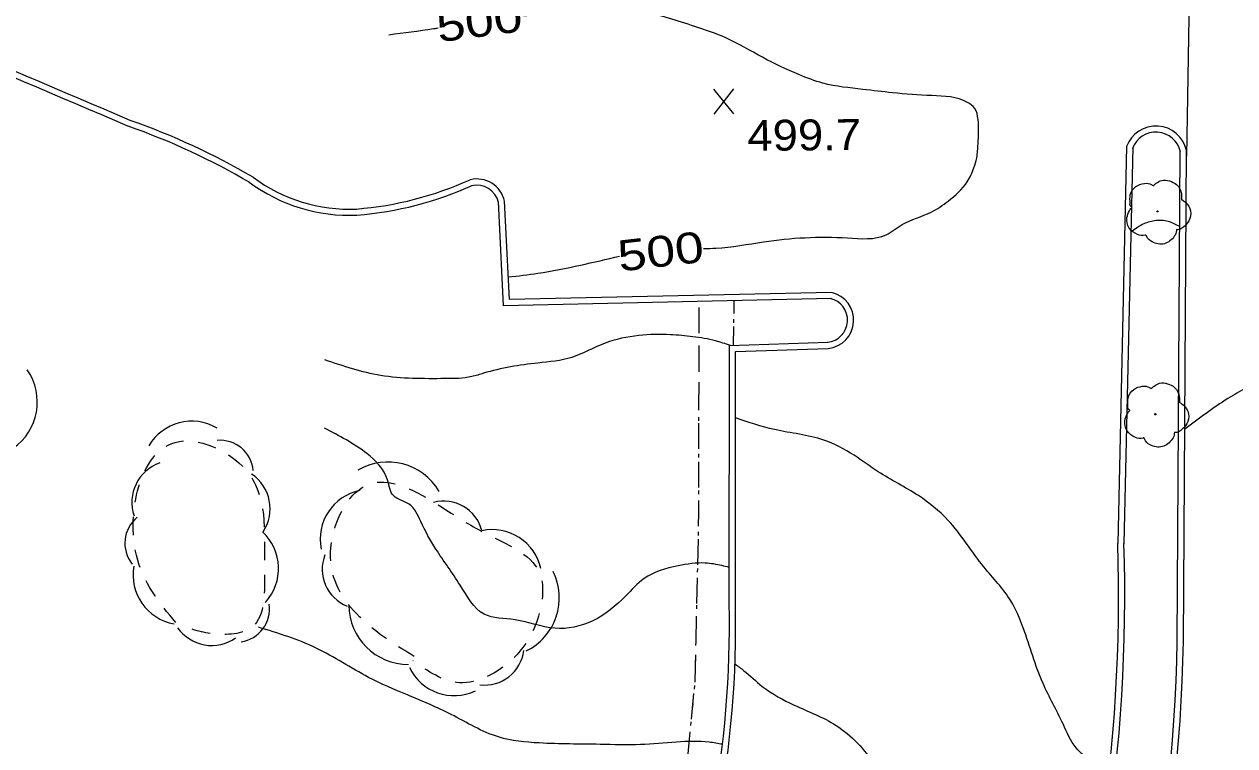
# Model space of a CAD drawing. Extents: x 2362213 to 2366494, y 6968794 to 6978110.
# Drawn here: x 2364033.7 to 2364221.6, y 6973266.2 to 6973378.3 of the extents above; entities that cross this region are included whole.
import ezdxf
from ezdxf.enums import TextEntityAlignment as Align

# ---------------------------------------------------------------- set-up
doc = ezdxf.new("R2010")
doc.units = 0
doc.header["$LTSCALE"] = 1.9
doc.linetypes.add('DOTTED', pattern=[1.5, 0.3, -1.2])
doc.linetypes.add('SHORT_DASHED', pattern=[2.7, 1.5, -1.2])
for name, color, linetype, lineweight in [('13', 7, 'Continuous', 13), ('2', 7, 'Continuous', 25), ('29', 7, 'Continuous', 13), ('31', 7, 'Continuous', 25), ('35', 7, 'Continuous', 13)]:
    doc.layers.add(name, color=color, linetype=linetype, lineweight=lineweight)

msp = doc.modelspace()

# ---------------------------------------------------------------- linework, layer by layer
at = {"layer": '13'}
for p, q in [((2364138.453, 6973330.3), (2364138.465, 6973334.301)), ((2364143.856, 6973335.322), (2364143.825, 6973333.322)), ((2364143.784, 6973331.321), (2364143.732, 6973328.391)), ((2364138.44, 6973324.301), (2364138.452, 6973328.3)), ((2364138.434, 6973312.299), (2364138.426, 6973316.3)), ((2364138.431, 6973306.299), (2364138.433, 6973310.299)), ((2364138.246, 6973294.297), (2364138.338, 6973298.299)), ((2364138.103, 6973288.295), (2364138.195, 6973292.296)), ((2364137.97, 6973282.294), (2364138.062, 6973286.295)), ((2364137.837, 6973276.293), (2364137.929, 6973280.293)), ((2364137.265, 6973270.316), (2364137.656, 6973274.301)), ((2364136.692, 6973264.341), (2364137.074, 6973268.325))]:
    msp.add_line(p, q, dxfattribs=at)
at = {"layer": '13', "linetype": 'DOTTED'}
msp.add_line((2364143.856, 6973335.322), (2364143.732, 6973328.391), dxfattribs=at)
msp.add_lwpolyline([(2364128.747, 6973249.094), (2364134.216, 6973248.096), (2364136.355, 6973260.807), (2364137.829, 6973276.053), (2364138.428, 6973302.43), (2364138.428, 6973319.271), (2364138.466, 6973335.201)], dxfattribs=at)
at = {"layer": '13'}
for points in [[(2364138.427, 6973318.301), (2364138.428, 6973319.271), (2364138.439, 6973322.301)], [(2364138.378, 6973300.299), (2364138.428, 6973302.43), (2364138.43, 6973304.299)]]:
    msp.add_lwpolyline(points, dxfattribs=at)
at = {"layer": '2'}
for p, q in [((2364214.964, 6973407.354), (2364214.125, 6973357.812)), ((2364204.831, 6973359.284), (2364203.448, 6973297.589)), ((2364205.791, 6973359.263), (2364204.408, 6973297.568)), ((2364212.704, 6973282.375), (2364213.167, 6973358.673)), ((2364213.664, 6973282.374), (2364214.127, 6973358.672))]:
    msp.add_line(p, q, dxfattribs=at)
for points in [[(2364159.034, 6973335.657), (2364108.082, 6973334.521), (2364107.278, 6973350.755)], [(2364159.015, 6973336.617), (2364108.993, 6973335.5), (2364108.237, 6973350.804)], [(2364143.125, 6973288.233), (2364143.152, 6973328.375), (2364158.448, 6973328.881)], [(2364144.085, 6973288.232), (2364144.111, 6973327.444), (2364158.477, 6973327.921)]]:
    msp.add_lwpolyline(points, dxfattribs=at)
for centre, radius, start, end in [((2297834.183, 6817959.898), 168921.461, 66.92161, 66.96926), ((2297834.183, 6817959.898), 168922.421, 66.92161, 66.96926), ((2364013.639, 6973259.63), 108.991, 59.65961, 70.61999), ((2364013.639, 6973259.63), 109.951, 59.65961, 70.61999), ((2364209.392, 6973357.644), 4.846, 12.25931, 160.2178), ((2364209.392, 6973357.644), 3.886, 12.25931, 160.2178), ((2364084.175, 6973374.709), 26.107, 233.39337, 272.44355), ((2364084.175, 6973374.709), 25.147, 233.39337, 272.44355), ((2364080.988, 6973402.517), 53.103, 274.60096, 294.36447), ((2364080.988, 6973402.517), 54.063, 274.60096, 294.36447), ((2364103.895, 6973349.8), 4.456, 13.01878, 102.97451), ((2364103.895, 6973349.8), 3.496, 13.01878, 102.97451), ((2364158.046, 6973332.312), 4.412, 275.6107, 77.31998), ((2364158.046, 6973332.312), 3.452, 275.6107, 77.31998), ((2363953.796, 6973289.236), 249.792, 340.34724, 1.91609), ((2363953.796, 6973289.236), 250.751, 340.34724, 1.91609), ((2363987.106, 6973284.72), 156.058, 349.19153, 1.28189), ((2363987.106, 6973284.72), 157.018, 349.19153, 1.28189), ((2363956.023, 6973287.24), 256.726, 337.03921, 358.91818), ((2363956.023, 6973287.24), 257.686, 337.03921, 358.91818)]:
    msp.add_arc(centre, radius, start, end, dxfattribs=at)
at = {"layer": '29'}
for centre in [(2364209.627, 6973349.22), (2364209.307, 6973317.695)]:
    msp.add_circle(centre, 0.1, dxfattribs=at)
for centre, radius, start, end in [((2364026.934, 6973319.593), 8.752, 304.69454, 34.69454), ((2364059.679, 6973308.859), 7.753, 59.56106, 149.56106), ((2364064.079, 6973308.476), 5.166, 5.44951, 95.44951), ((2364056.823, 6973304.011), 6.464, 109.04846, 199.04846), ((2364090.111, 6973301.043), 9.229, 30.36454, 120.36454), ((2364065.369, 6973303.019), 6.464, 326.23929, 56.23929), ((2364087.311, 6973298.301), 7.695, 101.72212, 191.72212), ((2364098.766, 6973298.051), 6.149, 14.7648, 104.7648), ((2364054.442, 6973297.657), 5.166, 128.81509, 218.81509), ((2364065.394, 6973293.718), 7.753, 317.34024, 47.34024), ((2364106.362, 6973292.064), 7.695, 12.28627, 102.28627), ((2364086.078, 6973293.598), 6.149, 158.47976, 248.47976), ((2364058.3, 6973292.743), 7.753, 169.8632, 259.8632), ((2364107.505, 6973289.168), 9.229, 296.44624, 26.44624), ((2364066.564, 6973287.421), 5.166, 278.5364, 8.5364), ((2364093.303, 6973288.043), 9.229, 180.10424, 270.10424), ((2364062.759, 6973288.229), 6.464, 215.10849, 305.10849), ((2364105.134, 6973281.756), 6.149, 262.94759, 352.94759), ((2364100.421, 6973281.661), 7.695, 205.37072, 295.37072)]:
    msp.add_arc(centre, radius, start, end, dxfattribs=at)
for points in [[(2364205.661, 6973349.792), (2364205.681, 6973349.803), (2364205.6, 6973349.872), (2364205.364, 6973350.499), (2364205.402, 6973351.779), (2364206.29, 6973353.077), (2364207.594, 6973353.56), (2364208.716, 6973353.371), (2364208.948, 6973353.243), (2364209.018, 6973353.243), (2364209.067, 6973353.284), (2364209.415, 6973353.577), (2364210.281, 6973354.026), (2364211.492, 6973353.957), (2364212.607, 6973353.368), (2364213.341, 6973351.945), (2364213.349, 6973351.085)], [(2364213.339, 6973351.105), (2364214.479, 6973350.046), (2364214.764, 6973348.459), (2364214.057, 6973347.132), (2364213.402, 6973346.586), (2364212.734, 6973346.37), (2364212.584, 6973346.358), (2364212.565, 6973346.248), (2364212.244, 6973345.345), (2364210.705, 6973344.18), (2364208.811, 6973344.462), (2364207.912, 6973345.404), (2364207.841, 6973345.533), (2364207.721, 6973345.512), (2364206.51, 6973345.63), (2364205.241, 6973346.628), (2364204.896, 6973348.265), (2364205.266, 6973349.289), (2364205.592, 6973349.732), (2364205.661, 6973349.782)], [(2364205.341, 6973318.268), (2364205.361, 6973318.278), (2364205.281, 6973318.347), (2364205.045, 6973318.975), (2364205.082, 6973320.255), (2364205.97, 6973321.554), (2364207.275, 6973322.036), (2364208.396, 6973321.847), (2364208.628, 6973321.719), (2364208.698, 6973321.72), (2364208.747, 6973321.76), (2364209.095, 6973322.054), (2364209.961, 6973322.502), (2364211.172, 6973322.434), (2364212.288, 6973321.844), (2364213.021, 6973320.421), (2364213.029, 6973319.561)], [(2364213.019, 6973319.581), (2364214.159, 6973318.522), (2364214.445, 6973316.933), (2364213.737, 6973315.607), (2364213.082, 6973315.06), (2364212.414, 6973314.844), (2364212.264, 6973314.833), (2364212.245, 6973314.722), (2364211.924, 6973313.819), (2364210.385, 6973312.655), (2364208.491, 6973312.937), (2364207.592, 6973313.878), (2364207.521, 6973314.007), (2364207.401, 6973313.986), (2364206.191, 6973314.105), (2364204.922, 6973315.103), (2364204.576, 6973316.74), (2364204.946, 6973317.763), (2364205.272, 6973318.207), (2364205.341, 6973318.258)]]:
    msp.add_spline(points, degree=3, dxfattribs=at)
at = {"layer": '29', "linetype": 'SHORT_DASHED'}
for points in [[(2364057.198, 6973285.325), (2364051.077, 6973295.788), (2364057.082, 6973313.325), (2364068.042, 6973309.079), (2364070.948, 6973293.726), (2364069.025, 6973284.627), (2364062.915, 6973283.579), (2364057.582, 6973284.978)], [(2364094.209, 6973280.057), (2364086.7, 6973285.296), (2364081.282, 6973294.484), (2364087.394, 6973306.903), (2364099.143, 6973302.845), (2364105.399, 6973299.125), (2364113.606, 6973293.192), (2364113.512, 6973286.301), (2364109.415, 6973279.602), (2364101.23, 6973275.965), (2364094.006, 6973279.395)]]:
    msp.add_spline(points, degree=3, dxfattribs=at)
at = {"layer": '31', "lineweight": 13}
for p, q in [((2364143.86, 6973364.375), (2364140.742, 6973368.225)), ((2364140.779, 6973364.345), (2364143.823, 6973368.254))]:
    msp.add_line(p, q, dxfattribs=at)
at = {"layer": '31'}
for points in [[(2364139.148, 6973343.449), (2364141.057, 6973343.497), (2364148.459, 6973344.487), (2364161.503, 6973345.092), (2364167.48, 6973345.579), (2364169.975, 6973347.162), (2364174.486, 6973349.105), (2364177.12, 6973350.82), (2364180.092, 6973353.798), (2364181.121, 6973355.998), (2364181.566, 6973357.532), (2364181.766, 6973359.694), (2364181.77, 6973363.485), (2364181.243, 6973365.221), (2364180.154, 6973366.15), (2364174.584, 6973367.197), (2364168.49, 6973367.639), (2364163.893, 6973368.175), (2364157.665, 6973369.136), (2364153.932, 6973370.471), (2364148.276, 6973373.156), (2364142.626, 6973376.172), (2364137.779, 6973377.956), (2364129.519, 6973380.128), (2364121.198, 6973380.148), (2364112.022, 6973379.671), (2364111.243, 6973379.564)], [(2364097.93, 6973377.667), (2364097.211, 6973377.56), (2364090.29, 6973376.614)], [(2364108.819, 6973339.029), (2364113.424, 6973339.603), (2364120.021, 6973340.866), (2364126.099, 6973342.254)]]:
    msp.add_spline(points, degree=3, dxfattribs=at)
at = {"layer": '35'}
for points in [[(2364213.099, 6973346.873), (2364211.302, 6973347.636), (2364209.18, 6973347.756), (2364207.275, 6973347.158), (2364205.497, 6973346.001)], [(2364143.302, 6973328.377), (2364141.004, 6973329.095), (2364137.488, 6973329.731), (2364134.006, 6973330.058), (2364129.107, 6973329.921), (2364123.748, 6973328.71), (2364118.688, 6973326.522), (2364113.407, 6973325.653), (2364104.992, 6973324.063), (2364103.157, 6973323.535), (2364098.979, 6973323.225), (2364088.994, 6973323.72), (2364080.351, 6973326.137)], [(2364254.057, 6973308.47), (2364251.87, 6973310.28), (2364248.916, 6973313.842), (2364246.506, 6973315.919), (2364244.098, 6973317.746), (2364240.567, 6973319.953), (2364236.585, 6973322.256), (2364233.137, 6973323.033), (2364228.026, 6973323.144), (2364223.439, 6973321.75), (2364220.564, 6973320.133), (2364213.869, 6973315.398)], [(2364143.131, 6973293.903), (2364141.987, 6973294.172), (2364139.413, 6973294.568), (2364135.178, 6973294.128), (2364129.897, 6973292.147), (2364127.032, 6973289.45), (2364121.939, 6973285.591), (2364116.029, 6973284.435), (2364109.867, 6973285.756), (2364105.058, 6973286.631), (2364101.345, 6973291.135), (2364097.581, 6973296.741), (2364095.219, 6973301.048), (2364093.434, 6973303.711), (2364090.991, 6973305.047), (2364090.069, 6973307.479), (2364086.88, 6973311.569), (2364080.282, 6973315.526)], [(2364202.023, 6973261.353), (2364199.522, 6973263.539), (2364197, 6973265.855), (2364194.965, 6973269.566), (2364191.854, 6973275.878), (2364188.782, 6973284.478), (2364186.871, 6973288.68), (2364182.662, 6973293.98), (2364177.082, 6973301.248), (2364172.506, 6973305.044), (2364166.25, 6973308.764), (2364162.545, 6973311.309), (2364157.803, 6973313.684), (2364150.177, 6973315.301), (2364144.099, 6973317.144)], [(2364142.081, 6973266.402), (2364140.038, 6973266.743), (2364134.929, 6973266.744), (2364129.332, 6973266.361), (2364123.072, 6973266.391), (2364113.639, 6973266.611), (2364107.3, 6973267.541), (2364099.936, 6973271.051), (2364093.166, 6973274.068), (2364087.131, 6973276.81), (2364078.997, 6973281.352), (2364070.035, 6973284.597)], [(2364144.013, 6973278.902), (2364145.404, 6973277.845), (2364148.267, 6973275.392), (2364153.225, 6973272.499), (2364159.715, 6973269.34), (2364165.704, 6973263.187), (2364167.292, 6973260.272), (2364168.921, 6973256.138), (2364170.817, 6973252.436), (2364173.534, 6973246.431), (2364173.829, 6973243.853), (2364173.03, 6973238.426), (2364172.211, 6973236.188), (2364170.31, 6973234.269), (2364168.237, 6973232.481), (2364164.385, 6973229.323), (2364161.515, 6973227.215), (2364158.506, 6973225.117), (2364153.756, 6973221.951), (2364149.47, 6973217.37), (2364146.708, 6973214.354), (2364141.817, 6973212.277), (2364138.511, 6973211.836), (2364133.285, 6973212.566), (2364129.075, 6973213.596)]]:
    msp.add_spline(points, degree=3, dxfattribs=at)

# ---------------------------------------------------------------- texts
at = {"layer": '31', "width": 1.25}
for rotation, p in [(7.529, (2364104.635, 6973376.363)), (6.576, (2364132.756, 6973340.627))]:
    msp.add_text(' 500 ', height=4.8, rotation=rotation, dxfattribs=at).set_placement(p, align=Align.CENTER)
at = {"layer": '31', "width": 1.1}
msp.add_text('499.7', height=4.8, rotation=0.546, dxfattribs=at).set_placement((2364145.965, 6973358.603))

doc.saveas('drawing.dxf')
